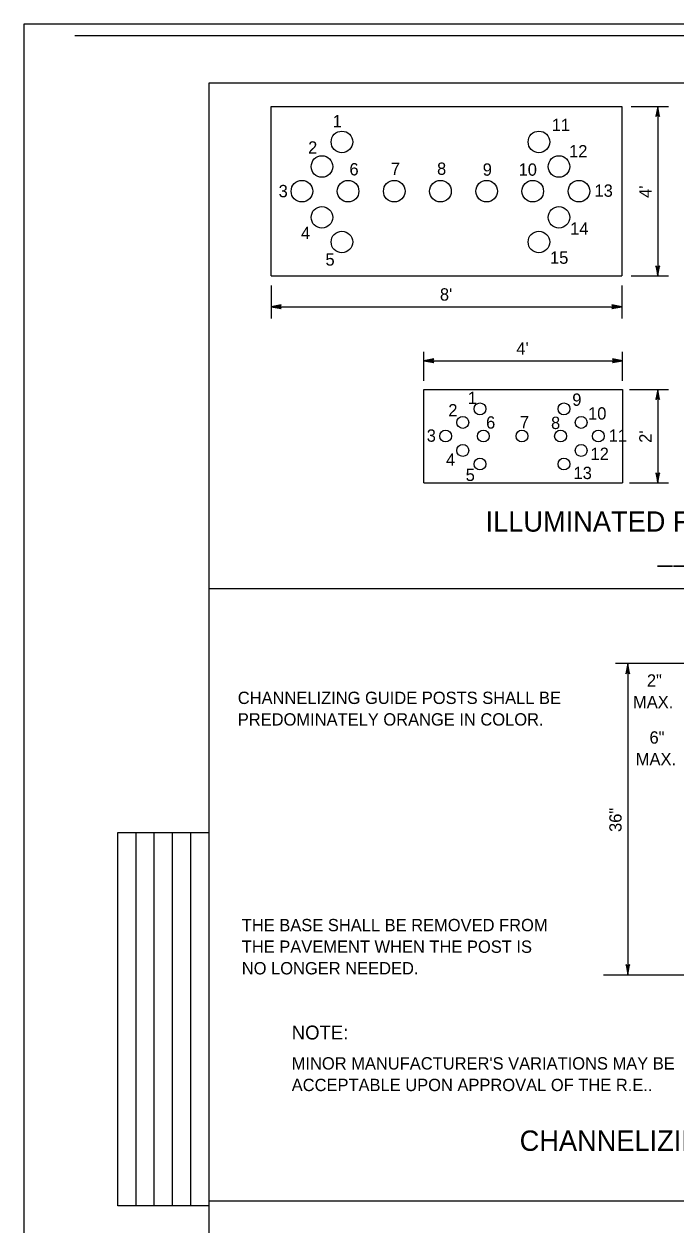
# Model space of a CAD drawing. Extents: x 499940 to 501012, y 499990 to 500649.
# Drawn here: x 499940 to 500151.3, y 500259.8 to 500649.2 of the extents above; entities that cross this region are included whole.
import ezdxf

# ---------------------------------------------------------------- set-up
doc = ezdxf.new("R2010")
doc.units = 0
for name, color, linetype in [('1', 7, 'Continuous'), ('10', 7, 'Continuous'), ('24', 7, 'Continuous'), ('41', 7, 'Continuous'), ('5', 7, 'Continuous'), ('60', 7, 'Continuous')]:
    doc.layers.add(name, color=color, linetype=linetype)

msp = doc.modelspace()

# ---------------------------------------------------------------- linework, layer by layer
at = {"layer": '1'}
for p, q in [((500000, 500630), (500000, 500000)), ((500990, 500630), (500000, 500630)), ((499970.47, 500265.75), (499970.47, 500386.81)), ((499970.47, 500386.81), (500000, 500386.81)), ((499976.38, 500265.75), (499976.38, 500386.81)), ((499982.28, 500265.75), (499982.28, 500386.81)), ((499988.19, 500265.75), (499988.19, 500386.81)), ((499994.09, 500265.75), (499994.09, 500386.81)), ((500000, 500265.75), (499970.47, 500265.75))]:
    msp.add_line(p, q, dxfattribs=at)
msp.add_lwpolyline([(499956.44, 500645.46), (500590.04, 500645.46), (501001.61, 500645.46)], dxfattribs=at)
at = {"layer": '10'}
for p, q in [((500000, 500466.05), (500339.52, 500466.05)), ((500000, 500267.34), (500339.52, 500267.34))]:
    msp.add_line(p, q, dxfattribs=at)
at = {"layer": '24'}
for points in [[(500145.7, 500622.4), (500145.12, 500619.13), (500145.7, 500619.91), (500146.27, 500619.15), (500145.7, 500622.4), (500145.7, 500622.19), (500145.16, 500619.22), (500145.7, 500619.97), (500146.22, 500619.28), (500145.71, 500622.07), (500145.7, 500621.96), (500145.25, 500619.42), (500145.7, 500619.99), (500146.15, 500619.4), (500145.7, 500621.91), (500145.71, 500621.8), (500145.31, 500619.58), (500145.7, 500620.01), (500146.1, 500619.57), (500145.71, 500621.49), (500145.71, 500621.3), (500145.4, 500619.75), (500145.69, 500620.05), (500146.01, 500619.72), (500145.7, 500621.27), (500145.69, 500621.09), (500145.49, 500619.92), (500145.71, 500620.15), (500145.94, 500619.9), (500145.7, 500620.93), (500145.68, 500620.77), (500145.55, 500620.06), (500145.7, 500620.18), (500145.88, 500619.99), (500145.7, 500620.68), (500145.59, 500620.22), (500145.71, 500620.29), (500145.84, 500620.09), (500145.71, 500620.57), (500145.64, 500620.27), (500145.74, 500620.39), (500145.8, 500620.25), (500145.7, 500620.39), (500145.69, 500620.32)], [(500145.7, 500567.45), (500146.28, 500570.72), (500145.7, 500569.94), (500145.13, 500570.7), (500145.7, 500567.45), (500145.69, 500567.66), (500146.23, 500570.63), (500145.69, 500569.88), (500145.17, 500570.57), (500145.68, 500567.78), (500145.7, 500567.89), (500146.15, 500570.43), (500145.69, 500569.86), (500145.25, 500570.44), (500145.7, 500567.94), (500145.68, 500568.05), (500146.08, 500570.27), (500145.7, 500569.84), (500145.3, 500570.28), (500145.68, 500568.36), (500145.68, 500568.55), (500146, 500570.1), (500145.71, 500569.8), (500145.38, 500570.13), (500145.7, 500568.58), (500145.71, 500568.76), (500145.91, 500569.93), (500145.68, 500569.7), (500145.46, 500569.94), (500145.7, 500568.92), (500145.71, 500569.08), (500145.85, 500569.78), (500145.69, 500569.67), (500145.52, 500569.86), (500145.7, 500569.17), (500145.81, 500569.63), (500145.68, 500569.56), (500145.56, 500569.76), (500145.68, 500569.28), (500145.76, 500569.58), (500145.66, 500569.46), (500145.6, 500569.6), (500145.69, 500569.46), (500145.71, 500569.53)], [(500020.21, 500557.43), (500023.48, 500556.85), (500022.7, 500557.43), (500023.47, 500558), (500020.21, 500557.43), (500020.43, 500557.44), (500023.39, 500556.89), (500022.64, 500557.44), (500023.33, 500557.95), (500020.54, 500557.45), (500020.65, 500557.43), (500023.19, 500556.98), (500022.62, 500557.44), (500023.21, 500557.88), (500020.7, 500557.43), (500020.81, 500557.45), (500023.03, 500557.04), (500022.6, 500557.43), (500023.04, 500557.83), (500021.13, 500557.45), (500021.31, 500557.45), (500022.87, 500557.13), (500022.56, 500557.42), (500022.89, 500557.75), (500021.35, 500557.43), (500021.52, 500557.42), (500022.69, 500557.22), (500022.46, 500557.45), (500022.71, 500557.67), (500021.68, 500557.43), (500021.85, 500557.41), (500022.55, 500557.28), (500022.43, 500557.44), (500022.62, 500557.61), (500021.93, 500557.43), (500022.39, 500557.32), (500022.32, 500557.45), (500022.52, 500557.57), (500022.05, 500557.45), (500022.35, 500557.37), (500022.22, 500557.47), (500022.37, 500557.53), (500022.22, 500557.44), (500022.3, 500557.42)], [(500134.06, 500557.43), (500130.79, 500558.01), (500131.57, 500557.43), (500130.81, 500556.86), (500134.06, 500557.43), (500133.85, 500557.42), (500130.88, 500557.97), (500131.63, 500557.42), (500130.94, 500556.9), (500133.73, 500557.41), (500133.62, 500557.43), (500131.08, 500557.88), (500131.65, 500557.42), (500131.06, 500556.98), (500133.57, 500557.43), (500133.46, 500557.41), (500131.24, 500557.81), (500131.67, 500557.43), (500131.23, 500557.03), (500133.14, 500557.41), (500132.96, 500557.41), (500131.4, 500557.73), (500131.71, 500557.44), (500131.38, 500557.11), (500132.93, 500557.43), (500132.75, 500557.44), (500131.58, 500557.64), (500131.81, 500557.41), (500131.56, 500557.19), (500132.59, 500557.43), (500132.43, 500557.45), (500131.72, 500557.58), (500131.84, 500557.42), (500131.65, 500557.25), (500132.34, 500557.43), (500131.88, 500557.54), (500131.95, 500557.41), (500131.75, 500557.29), (500132.23, 500557.41), (500131.92, 500557.49), (500132.05, 500557.39), (500131.91, 500557.33), (500132.05, 500557.42), (500131.97, 500557.44)], [(500069.74, 500539.92), (500073.01, 500539.34), (500072.23, 500539.92), (500073, 500540.49), (500069.74, 500539.92), (500069.96, 500539.92), (500072.92, 500539.38), (500072.17, 500539.93), (500072.87, 500540.44), (500070.08, 500539.93), (500070.18, 500539.92), (500072.72, 500539.47), (500072.15, 500539.92), (500072.74, 500540.37), (500070.23, 500539.92), (500070.34, 500539.93), (500072.56, 500539.53), (500072.13, 500539.92), (500072.57, 500540.32), (500070.66, 500539.93), (500070.84, 500539.93), (500072.4, 500539.62), (500072.1, 500539.91), (500072.42, 500540.23), (500070.88, 500539.92), (500071.05, 500539.91), (500072.22, 500539.71), (500072, 500539.93), (500072.24, 500540.16), (500071.21, 500539.92), (500071.38, 500539.9), (500072.08, 500539.77), (500071.96, 500539.93), (500072.15, 500540.1), (500071.46, 500539.92), (500071.92, 500539.81), (500071.85, 500539.93), (500072.06, 500540.06), (500071.58, 500539.93), (500071.88, 500539.86), (500071.75, 500539.96), (500071.9, 500540.02), (500071.75, 500539.93), (500071.83, 500539.91)], [(500134.27, 500539.92), (500131, 500540.5), (500131.78, 500539.92), (500131.01, 500539.35), (500134.27, 500539.92), (500134.05, 500539.91), (500131.09, 500540.45), (500131.84, 500539.91), (500131.14, 500539.39), (500133.93, 500539.9), (500133.83, 500539.92), (500131.29, 500540.37), (500131.86, 500539.91), (500131.27, 500539.47), (500133.78, 500539.92), (500133.67, 500539.9), (500131.45, 500540.3), (500131.88, 500539.92), (500131.44, 500539.52), (500133.35, 500539.9), (500133.17, 500539.9), (500131.61, 500540.22), (500131.91, 500539.93), (500131.59, 500539.6), (500133.13, 500539.92), (500132.96, 500539.93), (500131.79, 500540.13), (500132.01, 500539.9), (500131.77, 500539.68), (500132.8, 500539.92), (500132.63, 500539.93), (500131.93, 500540.07), (500132.05, 500539.91), (500131.85, 500539.74), (500132.55, 500539.92), (500132.09, 500540.03), (500132.16, 500539.9), (500131.95, 500539.78), (500132.43, 500539.9), (500132.13, 500539.98), (500132.26, 500539.88), (500132.11, 500539.82), (500132.26, 500539.91), (500132.18, 500539.93)], [(500145.7, 500530.56), (500145.12, 500527.29), (500145.7, 500528.07), (500146.27, 500527.3), (500145.7, 500530.56), (500145.7, 500530.34), (500145.16, 500527.38), (500145.7, 500528.13), (500146.22, 500527.44), (500145.71, 500530.23), (500145.7, 500530.12), (500145.25, 500527.58), (500145.7, 500528.15), (500146.15, 500527.56), (500145.7, 500530.07), (500145.71, 500529.96), (500145.31, 500527.74), (500145.7, 500528.17), (500146.1, 500527.73), (500145.71, 500529.64), (500145.71, 500529.46), (500145.4, 500527.9), (500145.69, 500528.2), (500146.01, 500527.88), (500145.7, 500529.42), (500145.69, 500529.25), (500145.49, 500528.08), (500145.71, 500528.3), (500145.94, 500528.06), (500145.7, 500529.09), (500145.68, 500528.92), (500145.55, 500528.22), (500145.7, 500528.34), (500145.88, 500528.15), (500145.7, 500528.84), (500145.59, 500528.38), (500145.71, 500528.45), (500145.84, 500528.25), (500145.71, 500528.72), (500145.64, 500528.42), (500145.74, 500528.55), (500145.8, 500528.4), (500145.7, 500528.55), (500145.69, 500528.47)], [(500145.7, 500500.26), (500146.28, 500503.54), (500145.7, 500502.76), (500145.13, 500503.52), (500145.7, 500500.26), (500145.69, 500500.48), (500146.23, 500503.45), (500145.69, 500502.69), (500145.17, 500503.39), (500145.68, 500500.6), (500145.7, 500500.71), (500146.15, 500503.25), (500145.69, 500502.68), (500145.25, 500503.26), (500145.7, 500500.76), (500145.68, 500500.87), (500146.08, 500503.09), (500145.7, 500502.65), (500145.3, 500503.1), (500145.68, 500501.18), (500145.68, 500501.37), (500146, 500502.92), (500145.71, 500502.62), (500145.38, 500502.94), (500145.7, 500501.4), (500145.71, 500501.57), (500145.91, 500502.74), (500145.68, 500502.52), (500145.46, 500502.76), (500145.7, 500501.74), (500145.71, 500501.9), (500145.85, 500502.6), (500145.69, 500502.49), (500145.52, 500502.68), (500145.7, 500501.99), (500145.81, 500502.44), (500145.68, 500502.38), (500145.56, 500502.58), (500145.68, 500502.1), (500145.76, 500502.4), (500145.66, 500502.28), (500145.6, 500502.42), (500145.69, 500502.28), (500145.71, 500502.35)], [(500135.99, 500441.65), (500135.4, 500438.33), (500135.99, 500439.12), (500136.56, 500438.35), (500135.99, 500441.65), (500135.99, 500441.43), (500135.44, 500438.42), (500135.99, 500439.19), (500136.52, 500438.48), (500136, 500441.31), (500135.99, 500441.2), (500135.53, 500438.62), (500135.99, 500439.2), (500136.44, 500438.61), (500135.99, 500441.15), (500136, 500441.04), (500135.6, 500438.79), (500135.99, 500439.23), (500136.39, 500438.78), (500136, 500440.72), (500136, 500440.53), (500135.68, 500438.96), (500135.98, 500439.26), (500136.31, 500438.93), (500135.99, 500440.5), (500135.98, 500440.32), (500135.77, 500439.14), (500136, 500439.36), (500136.23, 500439.12), (500135.99, 500440.16), (500135.97, 500439.99), (500135.83, 500439.28), (500135.99, 500439.4), (500136.17, 500439.2), (500135.99, 500439.91), (500135.88, 500439.44), (500136, 500439.51), (500136.13, 500439.3), (500136, 500439.79), (500135.93, 500439.48), (500136.03, 500439.61), (500136.09, 500439.47), (500135.99, 500439.61), (500135.98, 500439.53)], [(500135.99, 500340.73), (500136.56, 500344), (500135.99, 500343.22), (500135.42, 500343.99), (500135.99, 500340.73), (500135.98, 500340.95), (500136.52, 500343.91), (500135.98, 500343.16), (500135.46, 500343.86), (500135.97, 500341.07), (500135.99, 500341.17), (500136.44, 500343.71), (500135.98, 500343.14), (500135.54, 500343.73), (500135.99, 500341.22), (500135.97, 500341.33), (500136.37, 500343.55), (500135.99, 500343.12), (500135.59, 500343.56), (500135.97, 500341.65), (500135.97, 500341.83), (500136.29, 500343.39), (500136, 500343.09), (500135.67, 500343.41), (500135.99, 500341.87), (500136, 500342.04), (500136.2, 500343.21), (500135.97, 500342.99), (500135.75, 500343.23), (500135.99, 500342.2), (500136, 500342.37), (500136.14, 500343.07), (500135.98, 500342.95), (500135.8, 500343.15), (500135.99, 500342.45), (500136.1, 500342.91), (500135.97, 500342.84), (500135.84, 500343.05), (500135.97, 500342.57), (500136.04, 500342.87), (500135.95, 500342.74), (500135.89, 500342.89), (500135.98, 500342.74), (500136, 500342.82)]]:
    msp.add_lwpolyline(points, dxfattribs=at)
at = {"layer": '41'}
msp.add_lwpolyline([(499939.98, 499990.18), (501000.54, 499990.18), (501000.54, 500649.16), (499939.98, 500649.16)], close=True, dxfattribs=at)
at = {"layer": '5'}
for p, q in [((500020.21, 500622.4), (500134.06, 500622.4)), ((500020.21, 500567.45), (500020.21, 500622.4)), ((500134.06, 500622.4), (500134.06, 500567.45)), ((500137.1, 500622.4), (500149.23, 500622.4)), ((500145.7, 500622.4), (500145.7, 500567.45)), ((500020.21, 500567.45), (500134.06, 500567.45)), ((500137.1, 500567.45), (500149.23, 500567.45)), ((500020.21, 500564.31), (500020.21, 500553.57)), ((500134.06, 500564.31), (500134.06, 500553.57)), ((500020.21, 500557.43), (500134.06, 500557.43)), ((500069.74, 500533.38), (500069.74, 500542.81)), ((500134.27, 500533.38), (500134.27, 500542.81)), ((500069.74, 500539.92), (500134.27, 500539.92)), ((500069.74, 500500.26), (500069.74, 500530.56)), ((500069.74, 500530.56), (500134.27, 500530.56)), ((500134.27, 500530.56), (500134.27, 500500.26)), ((500136.5, 500530.56), (500149.23, 500530.56)), ((500145.7, 500530.56), (500145.7, 500500.26)), ((500069.74, 500500.26), (500134.27, 500500.26)), ((500136.5, 500500.26), (500149.23, 500500.26)), ((500161.65, 500441.65), (500131.99, 500441.65)), ((500135.99, 500441.65), (500135.99, 500340.73)), ((500128.06, 500340.73), (500211.46, 500340.73))]:
    msp.add_line(p, q, dxfattribs=at)
at = {"layer": '60'}
for centre, radius in [((500043.19, 500610.91), 3.5), ((500107.14, 500610.91), 3.5), ((500036.7, 500602.92), 3.5), ((500113.64, 500602.92), 3.5), ((500030.2, 500594.92), 3.5), ((500045.19, 500594.92), 3.5), ((500060.18, 500594.92), 3.5), ((500075.17, 500594.92), 3.5), ((500090.16, 500594.92), 3.5), ((500105.14, 500594.92), 3.5), ((500120.13, 500594.92), 3.5), ((500036.7, 500586.43), 3.5), ((500113.64, 500586.43), 3.5), ((500043.19, 500578.44), 3.5), ((500107.14, 500578.44), 3.5), ((500088.01, 500524.3), 1.93), ((500115.27, 500524.3), 1.93), ((500082.43, 500519.89), 1.93), ((500120.85, 500519.89), 1.93), ((500076.85, 500515.48), 1.93), ((500089.11, 500515.48), 1.93), ((500101.64, 500515.48), 1.93), ((500114.17, 500515.48), 1.93), ((500126.43, 500515.48), 1.93), ((500082.43, 500510.8), 1.93), ((500120.85, 500510.8), 1.93), ((500088.01, 500506.4), 1.93), ((500115.27, 500506.4), 1.93)]:
    msp.add_circle(centre, radius, dxfattribs=at)

# ---------------------------------------------------------------- texts
at = {"layer": '5'}
for s, height, p in [('1', 4, (500040.17, 500615.61)), ('11', 4, (500111.29, 500614.42)), ('2', 4, (500032.22, 500607.1)), ('12', 4, (500116.93, 500605.89)), ('6', 4, (500045.63, 500600.05)), ('7', 4, (500059.08, 500600.22)), ('8', 4, (500074.07, 500600.22)), ('9', 4, (500088.9, 500599.94)), ('10', 4, (500100.54, 500599.94)), ('3', 4, (500022.64, 500592.96)), ('13', 4, (500125.18, 500593.11)), ('14', 4, (500117.28, 500580.8)), ('4', 4, (500029.91, 500579.39)), ('5', 4, (500037.85, 500570.76)), ('15', 4, (500110.74, 500571.37)), ("8'", 4, (500075, 500559.43)), ("4'", 4, (500099.83, 500541.92)), ('1', 4, (500084.08, 500525.88)), ('2', 4, (500077.72, 500521.85)), ('9', 4, (500117.97, 500525.29)), ('10', 4, (500123.1, 500520.82)), ('6', 4, (500089.99, 500517.88)), ('7', 4, (500100.97, 500517.98)), ('8', 4, (500111.07, 500517.76)), ('3', 4, (500070.72, 500513.63)), ('11', 4, (500129.79, 500513.61)), ('12', 4, (500123.9, 500507.72)), ('4', 4, (500077, 500505.86)), ('5', 4, (500083.37, 500500.9)), ('13', 4, (500118.38, 500501.52)), ('ILLUMINATED FLASHING ARROWS,', 6.6001, (500089.83, 500484.46)), ('____ x ____', 6.6001, (500145.74, 500474.86)), ('2"', 4, (500142.19, 500434.18)), ('CHANNELIZING GUIDE POSTS SHALL BE', 4, (500009.38, 500428.55)), ('MAX.', 4, (500137.69, 500427.18)), ('PREDOMINATELY ORANGE IN COLOR.', 4, (500009.38, 500421.55)), ('6"', 4, (500143.04, 500415.69)), ('MAX.', 4, (500138.58, 500408.69)), ('THE BASE SHALL BE REMOVED FROM', 4, (500010.68, 500354.82)), ('THE PAVEMENT WHEN THE POST IS', 4, (500010.68, 500347.82)), ('NO LONGER NEEDED.', 4, (500010.68, 500340.82)), ('NOTE:', 4.5, (500026.89, 500319.71)), ("MINOR MANUFACTURER'S VARIATIONS MAY BE", 4, (500026.89, 500309.96)), ('ACCEPTABLE UPON APPROVAL OF THE R.E..', 4, (500026.89, 500302.96)), ('CHANNELIZING GUIDE POSTS', 6.6001, (500100.89, 500283.58))]:
    msp.add_text(s, height=height, dxfattribs=at).set_placement(p)
for s, p in [("4'", (500143.7, 500592.75)), ("2'", (500143.7, 500513.28)), ('36"', (500133.99, 500387.03))]:
    msp.add_text(s, height=4, rotation=90, dxfattribs=at).set_placement(p)

doc.saveas('drawing.dxf')
